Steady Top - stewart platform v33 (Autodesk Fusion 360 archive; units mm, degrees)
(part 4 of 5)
base_feature "Base Feature1"
base_feature "Base Feature1"
base_feature "Base Feature1"
base_feature "Base Feature1"
base_feature "Base Feature1"
base_feature "Base Feature1"
base_feature "Base Feature1"
base_feature "Base Feature1"
base_feature "Base Feature1"
base_feature "Base Feature1"
base_feature "Base Feature1"
base_feature "Base Feature1"
base_feature "Base Feature1"
base_feature "Base Feature1"
base_feature "Base Feature1"
base_feature "Base Feature1"
base_feature "Base Feature1"
base_feature "Base Feature1"
base_feature "Base Feature1"
base_feature "Base Feature1"
base_feature "Base Feature1"
base_feature "Base Feature1"
base_feature "Base Feature1"
base_feature "Base Feature1"
base_feature "Base Feature1"
base_feature "Base Feature1"
base_feature "Base Feature1"
base_feature "Base Feature1"
base_feature "Base Feature1"
base_feature "Base Feature1"
base_feature "Base Feature1"
base_feature "Base Feature1"
base_feature "Base Feature1"
base_feature "Base Feature1"
base_feature "Base Feature1"
base_feature "Base Feature1"
base_feature "Base Feature1"
base_feature "Base Feature1"
base_feature "Base Feature1"
base_feature "Base Feature1"
base_feature "Base Feature1"
base_feature "Base Feature1"
box_primitive "BoxPrimitive1" DistanceX 21.955 DistanceY 11.279 DistanceZ 0.1 OffsetDistanceX 0 OffsetDistanceY 0
base_feature "Base Feature1"
base_feature "Base Feature1"
base_feature "Base Feature1"
base_feature "Base Feature1"
base_feature "Base Feature1"
base_feature "Base Feature1"
base_feature "Base Feature1"
base_feature "Base Feature1"
base_feature "Base Feature1"
base_feature "Base Feature1"
base_feature "Base Feature1"
base_feature "Base Feature1"
base_feature "Base Feature1"
base_feature "Base Feature1"
base_feature "Base Feature1"
base_feature "Base Feature1"
base_feature "Base Feature1"
base_feature "Base Feature1"
base_feature "Base Feature1"
base_feature "Base Feature1"
base_feature "Base Feature1"
base_feature "Base Feature1"
base_feature "Base Feature1"
base_feature "Base Feature1"
base_feature "Base Feature1"
base_feature "Base Feature1"
base_feature "Base Feature1"
base_feature "Base Feature1"
base_feature "Base Feature1"
base_feature "Base Feature1"
base_feature "Base Feature1"
base_feature "Base Feature1"
base_feature "Base Feature1"
base_feature "Base Feature1"
base_feature "Base Feature1"
base_feature "Base Feature1"
base_feature "Base Feature1"
base_feature "Base Feature1"
base_feature "Base Feature1"
base_feature "Base Feature1"
base_feature "Base Feature1"
base_feature "Base Feature1"
base_feature "Base Feature1"
base_feature "Base Feature1"
base_feature "Base Feature1"
base_feature "Base Feature1"
base_feature "Base Feature1"
base_feature "Base Feature1"
base_feature "Base Feature1"
base_feature "Base Feature1"
base_feature "Base Feature1"
base_feature "Base Feature1"
base_feature "Base Feature1"
base_feature "Base Feature1"
base_feature "Base Feature1"
base_feature "Base Feature1"
base_feature "Base Feature1"
base_feature "Base Feature1"
base_feature "Base Feature1"
base_feature "Base Feature1"
base_feature "Base Feature1"
box_primitive "BoxPrimitive1" DistanceX 16.34 DistanceY 13 DistanceZ 0.1 OffsetDistanceX 0 OffsetDistanceY 0
box_primitive "BoxPrimitive1" DistanceX 8 DistanceY 6.35 DistanceZ 0.1 OffsetDistanceX 0 OffsetDistanceY 0
box_primitive "BoxPrimitive1" DistanceX 8.89 DistanceY 6.248 DistanceZ 0.1 OffsetDistanceX 0 OffsetDistanceY 0
box_primitive "BoxPrimitive1" DistanceX 4.572 DistanceY 2.159 DistanceZ 0.1 OffsetDistanceX 0 OffsetDistanceY 0
box_primitive "BoxPrimitive1" DistanceX 4.997 DistanceY 2.017 DistanceZ 0.1 OffsetDistanceX 0 OffsetDistanceY 0
box_primitive "BoxPrimitive1" DistanceX 4.572 DistanceY 2.159 DistanceZ 0.1 OffsetDistanceX 0 OffsetDistanceY 0
box_primitive "BoxPrimitive1" DistanceX 2.54 DistanceY 6.35 DistanceZ 0.1 OffsetDistanceX 0 OffsetDistanceY 0
pcbextrude "PCBExtrude1"
pcbextrude "PCBExtrude1"
pcbextrude "PCBExtrude1"
pcbextrude "PCBExtrude1"
extrude "Extrude1" sketch "Outline(Sketch2)" blind 1.067 bodies "Board"
pcbextrude "PCBExtrude1"
pcbextrude "PCBExtrude2" bodies "CopperHoles"
create_component "CreateComponent1"
create_component "CreateComponent2"
create_component "CreateComponent3"
create_component "CreateComponent4"
create_component "CreateComponent5"
create_component "CreateComponent6"
as_built_joint "As-built1"
create_component "CreateComponent1"
create_component "CreateComponent2"
create_component "CreateComponent3"
create_component "CreateComponent5"
create_component "CreateComponent6"
create_component "CreateComponent7"
create_component "CreateComponent8"
create_component "CreateComponent10"
create_component "CreateComponent1"
create_component "CreateComponent1"
create_component "CreateComponent1"
create_component "CreateComponent2"
create_component "CreateComponent3"
create_component "CreateComponent4"
create_component "CreateComponent1"
create_component "CreateComponent2"
create_component "CreateComponent3"
create_component "CreateComponent4"
create_component "CreateComponent1"
create_component "CreateComponent2"
create_component "CreateComponent3"
create_component "CreateComponent4"
create_component "CreateComponent5"
create_component "CreateComponent6"
create_component "CreateComponent7"
create_component "CreateComponent8"
create_component "CreateComponent9"
create_component "CreateComponent10"
create_component "CreateComponent11"
create_component "CreateComponent12"
create_component "CreateComponent13"
create_component "CreateComponent2"
create_component "CreateComponent1"
create_component "CreateComponent1"
create_component "CreateComponent2"
create_component "CreateComponent2"
create_component "CreateComponent1"
create_component "CreateComponent2"
create_component "CreateComponent3"
create_component "CreateComponent1"
create_component "CreateComponent2"
create_component "CreateComponent3"
create_component "CreateComponent1"
create_component "CreateComponent1"
create_component "CreateComponent2"
create_component "CreateComponent2"
create_component "CreateComponent1"
create_component "CreateComponent2"
create_component "CreateComponent3"
create_component "CreateComponent1"
create_component "CreateComponent2"
create_component "CreateComponent4"
create_component "CreateComponent1"
create_component "CreateComponent2"
create_component "CreateComponent4"
create_component "CreateComponent1"
create_component "CreateComponent1"
create_component "CreateComponent2"
create_component "CreateComponent2"
create_component "CreateComponent1"
create_component "CreateComponent2"
create_component "CreateComponent3"
create_component "CreateComponent1"
create_component "CreateComponent2"
create_component "CreateComponent5"
create_component "CreateComponent1"
create_component "CreateComponent1"
create_component "CreateComponent2"
create_component "CreateComponent2"
create_component "CreateComponent1"
create_component "CreateComponent2"
create_component "CreateComponent3"
create_component "CreateComponent1"
create_component "CreateComponent2"
create_component "CreateComponent4"
create_component "CreateComponent1"
create_component "CreateComponent2"
create_component "CreateComponent6"
create_component "CreateComponent1"
create_component "CreateComponent1"
create_component "CreateComponent1"
create_component "CreateComponent2"
create_component "CreateComponent1"
create_component "CreateComponent3"
create_component "CreateComponent1"
create_component "CreateComponent2"
create_component "CreateComponent1"
create_component "CreateComponent1"
create_component "CreateComponent2"
create_component "CreateComponent1"
create_component "CreateComponent3"
create_component "CreateComponent1"
create_component "CreateComponent4"
create_component "CreateComponent1"
create_component "CreateComponent7"
create_component "CreateComponent1"
create_component "CreateComponent1"
create_component "CreateComponent1"
create_component "CreateComponent2"
create_component "CreateComponent1"
create_component "CreateComponent3"
create_component "CreateComponent1"
create_component "CreateComponent2"
create_component "CreateComponent1"
create_component "CreateComponent1"
create_component "CreateComponent2"
create_component "CreateComponent1"
create_component "CreateComponent3"
create_component "CreateComponent1"
create_component "CreateComponent4"
create_component "CreateComponent1"
create_component "CreateComponent13"
named bodies: "Board", "CopperHoles"

design "815 Servo Driver 16 Channel"
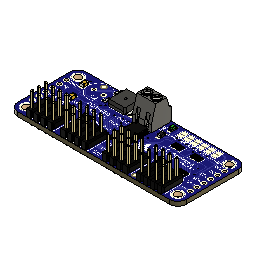
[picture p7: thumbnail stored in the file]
part number: PCA9685
part number: 10K
part number: MOUNTINGHOLE2.5
part number: FIDUCIAL""
part number: AOD417
part number: GREEN
part number: 470
pcb "PCB1" BoardHeight 1.57
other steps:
extrude "Extrude1" new body sketch "Sketch1" along normal blind 0.1 bodies "SOLDERJUMPER_REFLOW_NOPASTE"
extrude "Extrude1" new body sketch "Sketch1" along normal blind 0.1 bodies "MOUNTINGHOLE_2.5_PLATED"
extrude "Extrude1" new body sketch "Sketch1" along normal blind 0.1 bodies "FIDUCIAL_1MM"
extrude "Extrude1" new body sketch "Sketch1" along normal blind 0.1 bodies "E3,5-8"
extrude "Extrude1" new body sketch "Sketch1" along normal blind 0.1 bodies "ADAFRUIT_5MM"
extrude "Extrude1" new body sketch "Sketch1" along normal blind 0.1 bodies "1X06-CLEANBIG"
extrude "Extrude1" new body sketch "Sketch1" along normal blind 0.1 bodies "PCBFEAT-REV-040"
extrude "Extrude1" new body sketch "Sketch1" along normal blind 0.1 bodies "TESTPOINT_ROUND_1MM"
extrude "Extrude1" new body sketch "Sketch1" along normal blind 0.1 bodies "TSSOP28"
extrude "Extrude1" new body sketch "Sketch1" along normal blind 0.1 bodies "TO252"
extrude "Extrude1" new body sketch "Sketch1" along normal blind 0.1 bodies "3X04"
extrude "Extrude1" new body sketch "Sketch1" along normal blind 0.1 bodies "0805-NO"
extrude "Extrude1" new body sketch "Sketch1" along normal blind 0.1 bodies "CHIPLED_0805_NOOUTLINE"
extrude "Extrude1" new body sketch "Sketch1" along normal blind 0.1 bodies "_0805MP"
extrude "Extrude1" new body sketch "Sketch1" along normal blind 0.1 bodies "RESPACK_4X0603"
base_feature "Base Feature1" sketch "Sketch1"
base_feature "Base Feature1" sketch "Sketch1"
base_feature "Base Feature1" sketch "Sketch1"
extrude "Extrude1" new body sketch "Sketch1" along normal blind 1.57 bodies "Board"
base_feature "Base Feature1" sketch "Sketch1"
base_feature "Base Feature1" sketch "Sketch1"
base_feature "Base Feature1" sketch "Sketch1"
base_feature "Base Feature1" sketch "Sketch1"
extrude "Extrude2" sketch "Sketch2" blind 1.57
extrude "Extrude1" new body sketch "Sketch1" along normal blind 0.1 bodies "TERMBLOCK_1X2-3.5MM"
base_feature "Base Feature1" sketch "Sketch1"
create_component "CreateComponent1"
sketch "Sketch1" plane through (0, 0, 0) normal (0, 0, 1) x axis (1, 0, 0)
  line L1 (-1.905, 15.748) -> (-1.905, -3.302)
  line L2 (57.15, 18.923) -> (1.27, 18.923)
  line L3 (60.325, -3.302) -> (60.325, 15.748)
  line L4 (1.27, -6.477) -> (57.15, -6.477)
  arc A1 centre (1.27, -3.302) radius 3.175 clockwise from (1.27, -6.477) to (-1.905, -3.302)
  arc A2 centre (1.27, 15.748) radius 3.175 clockwise from (-1.905, 15.748) to (1.27, 18.923)
  arc A3 centre (57.15, 15.748) radius 3.175 clockwise from (57.15, 18.923) to (60.325, 15.748)
  arc A4 centre (57.15, -3.302) radius 3.175 clockwise from (60.325, -3.302) to (57.15, -6.477)
canvas "Canvas1"
canvas "Canvas2"
sketch "Sketch2" plane through (0, 0, 0) normal (0, 0, 1) x axis (1, 0, 0)
  circle C1 centre (15.24, -2.54) radius 0.25
  circle C2 centre (15.24, -1.27) radius 0.25
  circle C3 centre (15.24, -3.81) radius 0.25
  circle C4 centre (4.953, 16.637) radius 0.197
  circle C5 centre (27.94, 2.667) radius 0.197
  circle C6 centre (33.655, 9.144) radius 0.197
  circle C7 centre (46.482, 13.081) radius 0.197
  circle C8 centre (5.334, 6.731) radius 0.197
  circle C9 centre (50.419, 14.224) radius 0.197
  circle C10 centre (29.083, 10.16) radius 0.197
  circle C11 centre (47.879, 14.224) radius 0.197
  circle C12 centre (24.765, 10.922) radius 0.197
  circle C13 centre (45.339, 14.224) radius 0.197
  circle C14 centre (22.86, 10.795) radius 0.197
  circle C15 centre (42.799, 14.224) radius 0.197
  circle C16 centre (23.876, 9.017) radius 0.197
  circle C17 centre (40.259, 14.224) radius 0.197
  circle C18 centre (20.193, 10.287) radius 0.197
  circle C19 centre (38.989, 14.605) radius 0.197
  circle C20 centre (15.367, 11.811) radius 0.197
  circle C21 centre (30.48, 7.493) radius 0.197
  circle C22 centre (29.464, 6.223) radius 0.197
  circle C23 centre (14.478, 10.795) radius 0.197
  circle C24 centre (52.578, 8.636) radius 0.197
  circle C25 centre (28.575, 5.08) radius 0.197
  circle C26 centre (28.321, 9.017) radius 0.197
  circle C27 centre (53.848, 6.096) radius 0.197
  circle C28 centre (27.41, 15.113) radius 0.5
  circle C29 centre (30.91, 15.113) radius 0.5
  circle C30 centre (1.27, 15.748) radius 1.25
  circle C31 centre (1.27, -3.302) radius 1.25
  circle C32 centre (57.15, 15.748) radius 1.25
  circle C33 centre (57.15, -3.302) radius 1.25
  circle C34 centre (8.128, 14.732) radius 0.4065
  circle C35 centre (11.684, 14.732) radius 0.4065
  circle C36 centre (0, 0) radius 0.508
  circle C37 centre (0, 2.54) radius 0.508
  circle C38 centre (0, 5.08) radius 0.508
  circle C39 centre (0, 7.62) radius 0.508
  circle C40 centre (0, 10.16) radius 0.508
  circle C41 centre (0, 12.7) radius 0.508
  circle C42 centre (58.42, 0) radius 0.508
  circle C43 centre (58.42, 2.54) radius 0.508
  circle C44 centre (58.42, 5.08) radius 0.508
  circle C45 centre (58.42, 7.62) radius 0.508
  circle C46 centre (58.42, 10.16) radius 0.508
  circle C47 centre (58.42, 12.7) radius 0.508
  circle C48 centre (25.4, 0) radius 0.5
  circle C49 centre (25.4, -2.54) radius 0.5
  circle C50 centre (22.86, 0) radius 0.5
  circle C51 centre (22.86, -2.54) radius 0.5
  circle C52 centre (20.32, 0) radius 0.5
  circle C53 centre (20.32, -2.54) radius 0.5
  circle C54 centre (17.78, 0) radius 0.5
  circle C55 centre (17.78, -2.54) radius 0.5
  circle C56 centre (25.4, -5.08) radius 0.5
  circle C57 centre (22.86, -5.08) radius 0.5
  circle C58 centre (20.32, -5.08) radius 0.5
  circle C59 centre (17.78, -5.08) radius 0.5
  circle C60 centre (12.7, 0) radius 0.5
  circle C61 centre (12.7, -2.54) radius 0.5
  circle C62 centre (10.16, 0) radius 0.5
  circle C63 centre (10.16, -2.54) radius 0.5
  circle C64 centre (7.62, 0) radius 0.5
  circle C65 centre (7.62, -2.54) radius 0.5
  circle C66 centre (5.08, 0) radius 0.5
  circle C67 centre (5.08, -2.54) radius 0.5
  circle C68 centre (12.7, -5.08) radius 0.5
  circle C69 centre (10.16, -5.08) radius 0.5
  circle C70 centre (7.62, -5.08) radius 0.5
  circle C71 centre (5.08, -5.08) radius 0.5
  circle C72 centre (53.34, 0) radius 0.5
  circle C73 centre (53.34, -2.54) radius 0.5
  circle C74 centre (50.8, 0) radius 0.5
  circle C75 centre (50.8, -2.54) radius 0.5
  circle C76 centre (48.26, 0) radius 0.5
  circle C77 centre (48.26, -2.54) radius 0.5
  circle C78 centre (45.72, 0) radius 0.5
  circle C79 centre (45.72, -2.54) radius 0.5
  circle C80 centre (53.34, -5.08) radius 0.5
  circle C81 centre (50.8, -5.08) radius 0.5
  circle C82 centre (48.26, -5.08) radius 0.5
  circle C83 centre (45.72, -5.08) radius 0.5
  circle C84 centre (40.64, 0) radius 0.5
  circle C85 centre (40.64, -2.54) radius 0.5
  circle C86 centre (38.1, 0) radius 0.5
  circle C87 centre (38.1, -2.54) radius 0.5
  circle C88 centre (35.56, 0) radius 0.5
  circle C89 centre (35.56, -2.54) radius 0.5
  circle C90 centre (33.02, 0) radius 0.5
  circle C91 centre (33.02, -2.54) radius 0.5
  circle C92 centre (40.64, -5.08) radius 0.5
  circle C93 centre (38.1, -5.08) radius 0.5
  circle C94 centre (35.56, -5.08) radius 0.5
  circle C95 centre (33.02, -5.08) radius 0.5
create_component "CreateComponent2" sketch "Sketch1"
sketch "Sketch1" plane through (0, 0, 0) normal (0, 0, 1) x axis (1, 0, 0)
  line L1 (4.465, -3.121) -> (-4.465, -3.121)
  line L2 (4.465, 3.121) -> (4.465, -3.121)
  line L3 (-4.465, 3.121) -> (4.465, 3.121)
  line L4 (-4.465, -3.121) -> (-4.465, 3.121)
create_component "CreateComponent3" sketch "Sketch1"
sketch "Sketch1" plane through (0, 0, 0) normal (0, 0, 1) x axis (1, 0, 0)
  line L1 (1.651, -1.016) -> (-1.651, -1.016)
  line L2 (1.651, 1.016) -> (1.651, -1.016)
  line L3 (-1.651, 1.016) -> (1.651, 1.016)
  line L4 (-1.651, -1.016) -> (-1.651, 1.016)
create_component "CreateComponent4" sketch "Sketch1"
sketch "Sketch1" plane through (0, 0, 0) normal (0, 0, 1) x axis (1, 0, 0)
  line L1 (1.106, -0.724) -> (-1.092, -0.724)
  line L2 (1.106, 0.726) -> (1.106, -0.724)
  line L3 (-1.092, 0.726) -> (1.106, 0.726)
  line L4 (-1.092, -0.724) -> (-1.092, 0.726)
create_component "CreateComponent5" sketch "Sketch1"
sketch "Sketch1" plane through (0, 0, 0) normal (0, 0, 1) x axis (1, 0, 0)
  line L1 (3.6, -3.6) -> (-3.4, -3.6)
  line L2 (3.6, 3.4) -> (3.6, -3.6)
  line L3 (-3.4, 3.4) -> (3.6, 3.4)
  line L4 (-3.4, -3.6) -> (-3.4, 3.4)
create_component "CreateComponent6" sketch "Sketch1"
sketch "Sketch1" plane through (0, 0, 0) normal (0, 0, 1) x axis (1, 0, 0)
  line L1 (2, -2) -> (-2, -2)
  line L2 (2, 2) -> (2, -2)
  line L3 (-2, 2) -> (2, 2)
  line L4 (-2, -2) -> (-2, 2)
create_component "CreateComponent7" sketch "Sketch1"
sketch "Sketch1" plane through (0, 0, 0) normal (0, 0, 1) x axis (1, 0, 0)
  line L1 (0.75, -0.75) -> (-0.75, -0.75)
  line L2 (0.75, 0.75) -> (0.75, -0.75)
  line L3 (-0.75, 0.75) -> (0.75, 0.75)
  line L4 (-0.75, -0.75) -> (-0.75, 0.75)
create_component "CreateComponent8" sketch "Sketch1"
sketch "Sketch1" plane through (0, 0, 0) normal (0, 0, 1) x axis (1, 0, 0)
  line L1 (3.277, -5.156) -> (-3.277, -5.156)
  line L2 (3.277, 5.105) -> (3.277, -5.156)
  line L3 (-3.277, 5.105) -> (3.277, 5.105)
  line L4 (-3.277, -5.156) -> (-3.277, 5.105)
create_component "CreateComponent9" sketch "Sketch1"
sketch "Sketch1" plane through (0, 0, 0) normal (0, 0, 1) x axis (1, 0, 0)
  line L1 (0.625, -1.3334) -> (-0.625, -1.3334)
  line L2 (0.625, 1.3334) -> (0.625, -1.3334)
  line L3 (-0.625, 1.3334) -> (0.625, 1.3334)
  line L4 (-0.625, -1.3334) -> (-0.625, 1.3334)
create_component "CreateComponent10" sketch "Sketch1"
sketch "Sketch1" plane through (0, 0, 0) normal (0, 0, 1) x axis (1, 0, 0)
  line L1 (1, -0.65) -> (-1, -0.65)
  line L2 (1, 0.65) -> (1, -0.65)
  line L3 (-1, 0.65) -> (1, 0.65)
  line L4 (-1, -0.65) -> (-1, 0.65)
create_component "CreateComponent11" sketch "Sketch1"
sketch "Sketch1" plane through (0, 0, 0) normal (0, 0, 1) x axis (1, 0, 0)
  line L1 (4.064, -4.064) -> (-4.064, -4.064)
  line L2 (4.064, 4.064) -> (4.064, -4.064)
  line L3 (-4.064, 4.064) -> (4.064, 4.064)
  line L4 (-4.064, -4.064) -> (-4.064, 4.064)
create_component "CreateComponent12" sketch "Sketch1"
sketch "Sketch1" plane through (0, 0, 0) normal (0, 0, 1) x axis (1, 0, 0)
  line L1 (4.873, -0.004) -> (-0.004, -0.004)
  line L2 (4.873, 4.865) -> (4.873, -0.004)
  line L3 (-0.004, 4.865) -> (4.873, 4.865)
  line L4 (-0.004, -0.004) -> (-0.004, 4.865)
create_component "CreateComponent13" sketch "Sketch1"
sketch "Sketch1" plane through (0, 0, 0) normal (0, 0, 1) x axis (1, 0, 0)
  line L1 (6.858, -0.508) -> (-6.858, -0.508)
  line L2 (6.858, 0.508) -> (6.858, -0.508)
  line L3 (-6.858, 0.508) -> (6.858, 0.508)
  line L4 (-6.858, -0.508) -> (-6.858, 0.508)
create_component "CreateComponent14" sketch "Sketch1"
sketch "Sketch1" plane through (0, 0, 0) normal (0, 0, 1) x axis (1, 0, 0)
  line L1 (5.08, -3.81) -> (-5.08, -3.81)
  line L2 (5.08, 3.81) -> (5.08, -3.81)
  line L3 (-5.08, 3.81) -> (5.08, 3.81)
  line L4 (-5.08, -3.81) -> (-5.08, 3.81)
create_component "CreateComponent15" sketch "Sketch1"
sketch "Sketch1" plane through (0, 0, 0) normal (0, 0, 1) x axis (1, 0, 0)
  line L1 (1.9, -1.4) -> (-1.9, -1.4)
  line L2 (1.9, 1.4) -> (1.9, -1.4)
  line L3 (-1.9, 1.4) -> (1.9, 1.4)
  line L4 (-1.9, -1.4) -> (-1.9, 1.4)
create_component "CreateComponent16" sketch "Sketch1"
sketch "Sketch1" plane through (0, 0, 0) normal (0, 0, 1) x axis (1, 0, 0)
  line L1 (0.898, -0.898) -> (-0.898, -0.898)
  line L2 (0.898, 0.898) -> (0.898, -0.898)
  line L3 (-0.898, 0.898) -> (0.898, 0.898)
  line L4 (-0.898, -0.898) -> (-0.898, 0.898)
create_component "CreateComponent17" sketch "Sketch1"
sketch "Sketch1" plane through (0, 0, 0) normal (0, 0, 1) x axis (1, 0, 0)
  line L1 (0.7, -0.7) -> (-0.7, -0.7)
  line L2 (0.7, 0.7) -> (0.7, -0.7)
  line L3 (-0.7, 0.7) -> (0.7, 0.7)
  line L4 (-0.7, -0.7) -> (-0.7, 0.7)
as_built_joint "As-built1"
named bodies: "Board", "TSSOP28", "SOLDERJUMPER_REFLOW_NOPASTE", "0805-NO", "TERMBLOCK_1X2-3.5MM", "MOUNTINGHOLE_2.5_PLATED", "FIDUCIAL_1MM", "TO252", "CHIPLED_0805_NOOUTLINE", "_0805MP", "E3,5-8", "ADAFRUIT_5MM", "1X06-CLEANBIG", "3X04", "RESPACK_4X0603", "PCBFEAT-REV-040", "TESTPOINT_ROUND_1MM"

design "SERVO ARM HORN WITH FASTENERS"
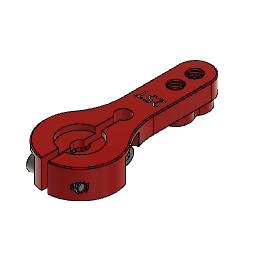
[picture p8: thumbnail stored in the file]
base_feature "Base Feature1"
base_feature "Base Feature1"
position "Position1"
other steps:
create_component "CreateComponent1"
create_component "CreateComponent2"

design "sunfounder_20kgSLDPRT"
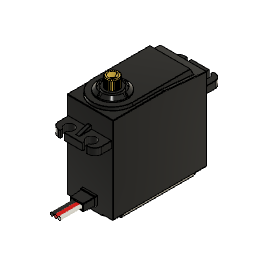
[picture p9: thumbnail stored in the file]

design "KCRM_10_3"
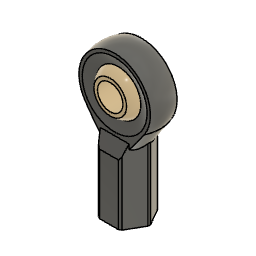
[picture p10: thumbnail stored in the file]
description: STEP AP214
description: PART-2025_05_17_16_37_46_0816-DESC
part number: 2025_05_17_16_37_46_0816
description: PART-2025_05_17_16_37_46_0832-DESC
part number: 2025_05_17_16_37_46_0832
base_feature "Base Feature1"
base_feature "Base Feature1"
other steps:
create_component "CreateComponent1"
create_component "CreateComponent2"

design "Fab Board"
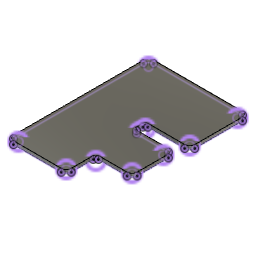
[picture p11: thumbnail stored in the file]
sketch "Sketch1" plane through (0, 0, 0) normal (0, 0, 1) x axis (1, 0, 0)
  line L1 (-17.5, 42.5) -> (17.5, 42.5)
  line L2 (-17.5, -42.5) -> (-17.5, 42.5)
  line L3 (17.5, -42.5) -> (-17.5, -42.5)
  line L4 (17.5, 42.5) -> (17.5, -42.5)
  line L5 (-17.5, -42.5) -> (17.5, 42.5)
  line L6 (17.5, -42.5) -> (-17.5, 42.5)
  line L7 (42.5, 42.5) -> (17.5, 42.5)
  line L8 (42.5, 7.5) -> (42.5, 42.5)
  line L9 (17.5, 7.5) -> (42.5, 7.5)
  line L10 (17.5, 42.5) -> (17.5, 7.5)
  line L11 (39.5, 0.5) -> (17.5, 0.5)
  line L12 (39.5, -24.5) -> (39.5, 0.5)
  line L13 (17.5, -24.5) -> (39.5, -24.5)
  line L14 (17.5, 0.5) -> (17.5, -24.5)
  point P6 (0, 0)
  point P1 (0, 0)
  point P13 (17.5, -24.5)
  point P4 (-17.5, -42.5)
  point P5 (17.5, -42.5)
  point P3 (-17.5, 42.5)
  point P2 (17.5, 42.5)
  point P7 (42.5, 42.5)
  point P11 (39.5, 0.5)
  point P12 (39.5, -24.5)
  horizontal L1
  perpendicular L1 L2
  parallel L1 L3
  parallel L2 L4
  coincident L5 P6
  coincident L6 P6
  coincident P1 P6
  horizontal L7
  vertical L8
  horizontal L9
  vertical L10
  horizontal L11
  vertical L12
  horizontal L13
  vertical L14
  equal L1 L8
  coincident L4 P13
  dimension "d1" distance P4 P5 = 35
  dimension "d2" distance P3 P4 = 85
  dimension "d3" distance P2 P7 = 25
  dimension "d8" distance P11 P12 = 25
  dimension "d9" distance L9 L11 = 7
  dimension "d10" distance L8 L12 = 3
extrude "Extrude1" new body sketch "Sketch1" profile of L1 L2 L3 L4 L7 L8 L9 L10 L11 L12 L13 L14 along normal blind 2
fillet "Fillet1" radius 3
fillet "Fillet2" radius 1.6
offset_faces "OffsetFaces1" distance -2
sketch "Sketch2" plane through (0, 0, 0) normal (0, 0, 1) x axis (1, 0, 0)
  line L1 (-14.5, 42.5) -> (39.5, 42.5)
  line L2 (-17.5, -39.5) -> (-17.5, 39.5)
  line L3 (14.5, -42.5) -> (-14.5, -42.5)
  line L4 (17.5, -26.1) -> (17.5, -39.5)
  line L5 (36.5, -24.5) -> (19.1, -24.5)
  line L6 (39.5, -2.5) -> (39.5, -21.5)
  line L7 (17.1, 0.5) -> (36.5, 0.5)
  line L8 (15.5, 5.9) -> (15.5, 2.1)
  line L9 (39.5, 7.5) -> (17.1, 7.5)
  line L10 (42.5, 39.5) -> (42.5, 10.5)
  arc A1 centre (39.5, 39.5) radius 3 clockwise from (39.5, 42.5) to (42.5, 39.5)
  arc A2 centre (-14.5, 39.5) radius 3 clockwise from (-17.5, 39.5) to (-14.5, 42.5)
  arc A3 centre (-14.5, -39.5) radius 3 clockwise from (-14.5, -42.5) to (-17.5, -39.5)
  arc A4 centre (14.5, -39.5) radius 3 clockwise from (17.5, -39.5) to (14.5, -42.5)
  arc A5 centre (36.5, -21.5) radius 3 clockwise from (39.5, -21.5) to (36.5, -24.5)
  arc A6 centre (36.5, -2.5) radius 3 clockwise from (36.5, 0.5) to (39.5, -2.5)
  arc A7 centre (39.5, 10.5) radius 3 clockwise from (42.5, 10.5) to (39.5, 7.5)
  arc A8 centre (19.1, -26.1) radius 1.6 clockwise from (17.5, -26.1) to (19.1, -24.5)
  arc A9 centre (17.1, 2.1) radius 1.6 clockwise from (17.1, 0.5) to (15.5, 2.1)
  arc A10 centre (17.1, 5.9) radius 1.6 clockwise from (15.5, 5.9) to (17.1, 7.5)

design "Meanwell RSP-150-7.5"
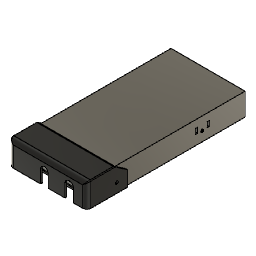
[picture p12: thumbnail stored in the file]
sketch "Sketch1" plane through (0, 0, 0) normal (0, 0, 1) x axis (1, 0, 0)
canvas "Canvas1"
sketch "Sketch2" plane through (0, 0, 0) normal (0, 0, 1) x axis (1, 0, 0)
  line L1 (49.5, -69.9887) -> (-49.5, -69.9887)
  line L2 (49.5, 129.0113) -> (49.5, -69.9887)
  line L3 (-49.5, 129.0113) -> (49.5, 129.0113)
  line L4 (-49.5, -69.9887) -> (-49.5, 129.0113)
  line L5 (-49.5, -55.2389) -> (49.5, -55.2389)
  line L6 (47.5, 129.0113) -> (47.5, -69.9887)
  line L7 (-47.5, -69.9887) -> (-47.5, 129.0113)
  line L8 (0, 129.0113) -> (0, 0)
  point P6 (49.5, -55.2389)
  point P7 (-49.5, -55.2389)
  point P8 (47.5, -69.9887)
  point P9 (47.5, 129.0113)
  point P10 (-47.5, 129.0113)
  point P11 (-47.5, -69.9887)
  point P1 (0, 0)
  point P12 (0, 0)
  point P13 (0, 129.0113)
  point P4 (49.5, 129.0113)
  point P5 (-49.5, 129.0113)
  point P2 (-49.5, -69.9887)
  horizontal L1
  vertical L2
  horizontal L3
  vertical L4
  coincident L2 P6
  coincident L4 P7
  perpendicular L4 L5
  coincident L1 P8
  coincident L3 P9
  perpendicular L3 L6
  coincident L3 P10
  coincident L1 P11
  perpendicular L1 L7
  coincident P1 P12
  midpoint L3 P13
  vertical L8
  dimension "d1" distance P4 P5 = 99
  dimension "d2" distance P2 P5 = 199
  dimension "d50" distance L4 L7 = 2
  dimension "d51" distance L2 L6 = 2
extrude "Extrude1" new body sketch "Sketch2" profile of L1 L2 L3 L4 L5 L6 L7 along normal blind 30
extrude "Extrude2" add sketch "Sketch2" profile of L1 L5 L6 L7 along normal blind 2
sketch "Sketch3" plane through (49.5, 0, 0) normal (1, 0, 0) x axis (0, 1, 0)
  line L1 (129.0113, 0) -> (-69.9887, 0)
  line L2 (129.0113, 30) -> (129.0113, 0)
  line L3 (-69.9887, 30) -> (129.0113, 30)
  line L4 (-69.9887, 0) -> (-69.9887, 30)
  line L5 (-44.9887, 30) -> (-44.9887, 0)
  line L6 (72.0113, 30) -> (72.0113, 0)
  line L7 (72.0113, 12.5) -> (-44.9887, 12.5)
  line L8 (129.0113, 0) -> (-69.9887, 0)
  line L9 (-35.9887, 13.1) -> (-38.4887, 13.1)
  line L10 (-35.9887, 20) -> (-35.9887, 13.1)
  line L11 (-38.4887, 20) -> (-35.9887, 20)
  line L12 (-38.4887, 13.1) -> (-38.4887, 20)
  line L13 (-51.4887, 13.1) -> (-51.4887, 20)
  line L14 (-53.9887, 13.1) -> (-51.4887, 13.1)
  line L15 (-51.4887, 20) -> (-53.9887, 20)
  line L16 (-53.9887, 20) -> (-53.9887, 13.1)
  line L17 (13.5113, 43.3895) -> (13.5113, 12.5)
  line L18 (81.0113, 20) -> (81.0113, 13.1)
  line L19 (78.5113, 20) -> (81.0113, 20)
  line L20 (78.5113, 13.1) -> (78.5113, 20)
  line L21 (81.0113, 13.1) -> (78.5113, 13.1)
  line L22 (65.5113, 13.1) -> (65.5113, 20)
  line L23 (63.0113, 13.1) -> (65.5113, 13.1)
  line L24 (65.5113, 20) -> (63.0113, 20)
  line L25 (63.0113, 20) -> (63.0113, 13.1)
  circle C1 centre (72.0113, 12.5) radius 2
  circle C2 centre (-44.9887, 12.5) radius 2
  point P6 (-44.9887, 0)
  point P7 (-44.9887, 30)
  point P8 (72.0113, 0)
  point P9 (72.0113, 30)
  point P10 (-44.9887, 12.5)
  point P11 (72.0113, 12.5)
  point P14 (72.0113, 12.5)
  point P15 (-44.9887, 12.5)
  point P16 (-38.4887, 13.1)
  point P21 (-51.4887, 13.1)
  point P17 (-35.9887, 13.1)
  point P22 (-53.9887, 13.1)
  point P18 (-35.9887, 20)
  point P23 (-53.9887, 20)
  point P19 (-38.4887, 20)
  point P20 (-51.4887, 20)
  point P24 (13.5113, 12.5)
  point P31 (65.5113, 13.1)
  point P32 (63.0113, 13.1)
  point P33 (63.0113, 20)
  point P30 (65.5113, 20)
  point P28 (78.5113, 20)
  point P29 (78.5113, 13.1)
  point P26 (81.0113, 13.1)
  point P27 (81.0113, 20)
  coincident L1 P6
  coincident L3 P7
  perpendicular L3 L5
  coincident L1 P8
  coincident L3 P9
  perpendicular L3 L6
  coincident L5 P10
  coincident L6 P11
  perpendicular L6 L7
  coincident P11 P14
  coincident P10 P15
  equal C1 C2
  horizontal L9
  vertical L10
  horizontal L11
  vertical L12
  symmetric L5 P16 P21
  symmetric L5 P17 P22
  symmetric L5 P18 P23
  symmetric L5 P19 P20
  midpoint L7 P24
  perpendicular L7 L17
  symmetric P16 L17 P31
  symmetric P17 L17 P32
  symmetric P18 L17 P33
  symmetric P19 L17 P30
  symmetric P20 L17 P28
  symmetric P21 L17 P29
  symmetric P22 L17 P26
  symmetric P23 L17 P27
  dimension "d7" distance L4 L5 = 25
  dimension "d8" distance L5 L6 = 117
  dimension "d9" distance L7 L8 = 12.5
  dimension "d10" diameter C1 = 4
  dimension "d15" distance P17 P18 = 6.9
  dimension "d16" distance P18 P19 = 2.5
  dimension "d17" distance L5 L12 = 6.5
  dimension "d19" distance L3 L11 = 10
extrude "Extrude3" cut sketch "Sketch3" profile of C1 C2 L9 L10 L11 L12 L13 L14 L15 L16 L18 L19 L20 L21 L22 L23 L24 L25 against normal blind 4
mirror "Mirror1" mirrorStitchTolerance 0.1
sketch "Sketch5" plane through (0, 0, 2) normal (0, 0, 1) x axis (-1, 0, 0)
  line L1 (47.5, 55.2389) -> (-47.5, 55.2389)
  line L2 (47.5, 69.9887) -> (47.5, 55.2389)
  line L3 (-47.5, 69.9887) -> (47.5, 69.9887)
  line L4 (-47.5, 55.2389) -> (-47.5, 69.9887)
  line L5 (-43.7071, 68.3467) -> (25.3054, 68.3467)
  line L6 (-43.7071, 53.8985) -> (-43.7071, 68.3467)
  line L7 (25.3054, 53.8985) -> (-43.7071, 53.8985)
  line L8 (25.3054, 68.3467) -> (25.3054, 53.8985)
  line L9 (15.433, 68.3467) -> (23.3131, 68.3467)
  line L10 (15.433, 55.2389) -> (15.433, 68.3467)
  line L11 (23.3131, 55.2389) -> (15.433, 55.2389)
  line L12 (23.3131, 68.3467) -> (23.3131, 55.2389)
  line L13 (13.7931, 68.3467) -> (13.7931, 55.2389)
  line L14 (5.913, 68.3467) -> (13.7931, 68.3467)
  line L15 (5.913, 55.2389) -> (5.913, 68.3467)
  line L16 (13.7931, 55.2389) -> (5.913, 55.2389)
  line L17 (4.2731, 68.3467) -> (4.2731, 55.2389)
  line L18 (-3.607, 68.3467) -> (4.2731, 68.3467)
  line L19 (-3.607, 55.2389) -> (-3.607, 68.3467)
  line L20 (4.2731, 55.2389) -> (-3.607, 55.2389)
  line L21 (-5.2469, 68.3467) -> (-5.2469, 55.2389)
  line L22 (-13.127, 68.3467) -> (-5.2469, 68.3467)
  line L23 (-13.127, 55.2389) -> (-13.127, 68.3467)
  line L24 (-5.2469, 55.2389) -> (-13.127, 55.2389)
  line L25 (-14.7669, 68.3467) -> (-14.7669, 55.2389)
  line L26 (-22.647, 68.3467) -> (-14.7669, 68.3467)
  line L27 (-22.647, 55.2389) -> (-22.647, 68.3467)
  line L28 (-14.7669, 55.2389) -> (-22.647, 55.2389)
  line L29 (-24.2869, 68.3467) -> (-24.2869, 55.2389)
  line L30 (-32.167, 68.3467) -> (-24.2869, 68.3467)
  line L31 (-32.167, 55.2389) -> (-32.167, 68.3467)
  line L32 (-24.2869, 55.2389) -> (-32.167, 55.2389)
  line L33 (-33.8069, 68.3467) -> (-33.8069, 55.2389)
  line L34 (-41.687, 68.3467) -> (-33.8069, 68.3467)
  line L35 (-41.687, 55.2389) -> (-41.687, 68.3467)
  line L36 (-33.8069, 55.2389) -> (-41.687, 55.2389)
  point P12 (15.433, 55.2389)
  point P10 (23.3131, 68.3467)
  horizontal L5
  vertical L6
  horizontal L7
  vertical L8
  horizontal L9
  vertical L10
  horizontal L11
  vertical L12
  coincident L1 P12
  coincident L5 P10
  dimension "d22" R-Pattern1-uDistance = -9.52
  dimension "d23" R-Pattern1-vDistance = 0
extrude "Extrude4" add sketch "Sketch5" profile of L1 L5 L6 L8 L10 L12 L13 L15 L17 L19 L21 L23 L25 L27 L29 L31 L32 L33 L35 along normal blind 19.5
extrude "Extrude5" add sketch "Sketch5" profile of L1 L5 L9 L10 L11 L12 L13 L14 L15 L16 L17 L18 L19 L20 L21 L22 L23 L24 L25 L26 L27 L28 L29 L30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 along normal blind 12
sketch "Sketch6" plane through (0, 0, 0) normal (0, 0, 1) x axis (1, 0, 0)
  line L1 (0, 65) -> (0, 0)
  circle C1 centre (0, 65) radius 2
  circle C2 centre (0, 0) radius 2
  point P1 (0, 0)
  point P3 (0, 0)
  point P4 (0, 0)
  point P2 (0, 65)
  point P5 (0, 65)
  coincident P1 P3
  coincident P1 P4
  coincident P2 P5
  vertical L1
  equal C1 C2
  dimension "d28" diameter C2 = 4
  dimension "d29" distance P4 P5 = 65
extrude "Extrude6" cut sketch "Sketch6" profile of C1 C2 along normal blind 4
thread "Thread1" ThreadOffset 0 ThreadLength 10
sketch "Sketch7" plane through (0, 0, 30) normal (0, 0, 1) x axis (-1, 0, 0)
  line L1 (-49.5, 69.9887) -> (-47.5, 69.9887)
  line L2 (-49.5, -129.0113) -> (-49.5, 69.9887)
  line L3 (49.5, -129.0113) -> (-49.5, -129.0113)
  line L4 (49.5, 69.9887) -> (49.5, -129.0113)
  line L5 (47.5, 69.9887) -> (49.5, 69.9887)
  line L6 (47.5, 55.2389) -> (47.5, 69.9887)
  line L7 (-47.5, 55.2389) -> (47.5, 55.2389)
  line L8 (-47.5, 69.9887) -> (-47.5, 55.2389)
  line L9 (-52, 44.9887) -> (52, 44.9887)
  line L10 (-52, 84.9887) -> (-52, 44.9887)
  line L11 (52, 84.9887) -> (-52, 84.9887)
  line L12 (52, 44.9887) -> (52, 84.9887)
  point P11 (-52, 44.9887)
  point P12 (-52, 84.9887)
  point P3 (-49.5, 69.9887)
  horizontal L9
  vertical L10
  horizontal L11
  vertical L12
  dimension "d34" distance L2 L10 = 2.5
  dimension "d35" distance L4 L12 = 2.5
  dimension "d36" distance P11 P12 = 40
  dimension "d37" distance P3 L9 = 25
extrude "Extrude7" new body sketch "Sketch7" profile of L1 L2 L4 L5 L6 L7 L8 L9 L10 L11 L12 along normal blind 2.5
sketch "Sketch8" plane through (49.5, 0, 0) normal (1, 0, 0) x axis (0, 1, 0)
  curve K1 (-46.2578, 13.5794) -> (-45.5189, 10.5148)
  curve K2 (-44.4586, 10.5148) -> (-43.7197, 13.5794)
  curve K3 (70.7422, 13.5794) -> (71.4811, 10.5148)
  curve K4 (72.5414, 10.5148) -> (73.2803, 13.5794)
  line L1 (-38.4887, 13.1) -> (-35.9887, 13.1)
  line L2 (-38.4887, 20) -> (-38.4887, 13.1)
  line L3 (-35.9887, 20) -> (-38.4887, 20)
  line L4 (-35.9887, 13.1) -> (-35.9887, 20)
  line L5 (65.5113, 13.1) -> (65.5113, 20)
  line L6 (63.0113, 13.1) -> (65.5113, 13.1)
  line L7 (63.0113, 20) -> (63.0113, 13.1)
  line L8 (65.5113, 20) -> (63.0113, 20)
  line L9 (-51.4887, 13.1) -> (-51.4887, 20)
  line L10 (-53.9887, 13.1) -> (-51.4887, 13.1)
  line L11 (-53.9887, 20) -> (-53.9887, 13.1)
  line L12 (-51.4887, 20) -> (-53.9887, 20)
  line L13 (81.0113, 13.1) -> (81.0113, 20)
  line L14 (78.5113, 13.1) -> (81.0113, 13.1)
  line L15 (78.5113, 20) -> (78.5113, 13.1)
  line L16 (81.0113, 20) -> (78.5113, 20)
  line L17 (129.0113, 0) -> (-69.9887, 0)
  line L18 (129.0113, 30) -> (129.0113, 0)
  line L19 (-69.9887, 30) -> (129.0113, 30)
  line L20 (-69.9887, 0) -> (-69.9887, 30)
  line L21 (-44.9887, 30) -> (-84.9887, 30)
  line L22 (-44.9887, 32.5) -> (-44.9887, 30)
  line L23 (-84.9887, 32.5) -> (-44.9887, 32.5)
  line L24 (-84.9887, 30) -> (-84.9887, 32.5)
  line L25 (-30.4006, 30) -> (-84.9887, 30)
  line L26 (-30.4006, 0) -> (-30.4006, 30)
  line L27 (-84.9887, 0) -> (-30.4006, 0)
  line L28 (-84.9887, 30) -> (-84.9887, 0)
  line L29 (-30.4006, 20.1056) -> (-48.6747, 32.5)
  arc A1 centre (-44.9887, 12.5) radius 1.666 clockwise from (-46.2578, 13.5794) to (-43.7197, 13.5794)
  arc A2 centre (-44.9887, 12.5) radius 2.0548 clockwise from (-44.4586, 10.5148) to (-45.5189, 10.5148)
  arc A3 centre (72.0113, 12.5) radius 1.666 clockwise from (70.7422, 13.5794) to (73.2803, 13.5794)
  arc A4 centre (72.0113, 12.5) radius 2.0548 clockwise from (72.5414, 10.5148) to (71.4811, 10.5148)
  circle C1 centre (-44.9887, 12.5) radius 2
  point P38 (-30.4006, 0)
  point P32 (-84.9887, 30)
  point P36 (-84.9887, 30)
  point P40 (-30.4006, 20.1056)
  point P41 (-48.6747, 32.5)
  horizontal L25
  vertical L26
  horizontal L27
  vertical L28
  coincident L17 P38
  coincident P32 P36
  coincident L26 P40
  coincident L23 P41
extrude "Extrude8" add sketch "Sketch8" profile of K1 K2 A2 L1 L2 L3 L4 L9 L10 L11 L12 L17 L19 L20 L21 L25 L26 L27 L28 L29 C1 along normal blind 2.5
sketch "Sketch9" plane through (49.5, 0, 0) normal (-1, 0, 0) x axis (0, -1, 0)
  line L1 (53.9887, 13.1) -> (53.9887, 20)
  line L2 (51.4887, 13.1) -> (53.9887, 13.1)
  line L3 (51.4887, 20) -> (51.4887, 13.1)
  line L4 (53.9887, 20) -> (51.4887, 20)
  line L5 (38.4887, 20) -> (35.9887, 20)
  line L6 (38.4887, 13.1) -> (38.4887, 20)
  line L7 (35.9887, 13.1) -> (38.4887, 13.1)
  line L8 (35.9887, 20) -> (35.9887, 13.1)
  curve K1 (44.4586, 10.5148) -> (43.9524, 10.7894)
  curve K2 (46.0251, 10.7894) -> (45.5189, 10.5148)
  line L9 (44.9887, 30) -> (84.9887, 30)
  line L10 (30.4006, 20.1056) -> (44.9887, 30)
  line L11 (30.4006, 0) -> (30.4006, 20.1056)
  line L12 (84.9887, 0) -> (30.4006, 0)
  line L13 (84.9887, 30) -> (84.9887, 0)
  line L14 (51.6637, 13.275) -> (53.8137, 13.275)
  line L15 (51.6637, 19.825) -> (51.6637, 13.275)
  line L16 (53.8137, 19.825) -> (51.6637, 19.825)
  line L17 (53.8137, 13.275) -> (53.8137, 19.825)
  line L18 (36.1637, 19.825) -> (36.1637, 13.275)
  line L19 (38.3137, 19.825) -> (36.1637, 19.825)
  line L20 (38.3137, 13.275) -> (38.3137, 19.825)
  line L21 (36.1637, 13.275) -> (38.3137, 13.275)
  arc A1 centre (44.9887, 12.5) radius 2.0548 clockwise from (45.5189, 10.5148) to (44.4586, 10.5148)
  arc A2 centre (44.9887, 12.5) radius 2 clockwise from (43.9524, 10.7894) to (46.0251, 10.7894)
  dimension "d42" = 0.175
  dimension "d43" = 0.175
extrude "Extrude9" add sketch "Sketch9" profile of L1 L2 L3 L4 L5 L6 L7 L8 L14 L15 L16 L17 L21 L20 L19 L18 against normal blind 2.5
extrude "Extrude10" add sketch "Sketch9" profile of L14 L15 L16 L17 L21 L20 L19 L18 along normal blind 1.5
mirror "Mirror2" mirrorStitchTolerance 0.1
chamfer "Chamfer1" distance 3.8 distance 2.5
sketch "Sketch10" plane through (0, -84.9887, 0) normal (0, -1, 0) x axis (1, 0, 0)
  line L1 (52, 32.5) -> (52, 0)
  line L2 (-52, 32.5) -> (52, 32.5)
  line L3 (-52, 0) -> (-52, 32.5)
  line L4 (-49.5, 0) -> (-52, 0)
  line L5 (-49.5, 30) -> (-49.5, 0)
  line L6 (49.5, 30) -> (-49.5, 30)
  line L7 (49.5, 0) -> (49.5, 30)
  line L8 (52, 0) -> (49.5, 0)
  line L9 (49.5, 0) -> (-49.5, 0)
  line L10 (34.0292, 22.5874) -> (22.6413, 22.5874)
  line L11 (34.0292, 0) -> (34.0292, 22.5874)
  line L12 (22.6413, 0) -> (34.0292, 0)
  line L13 (22.6413, 22.5874) -> (22.6413, 0)
  line L14 (0.1205, 22.5476) -> (-9.956, 22.5476)
  line L15 (0.1205, 0) -> (0.1205, 22.5476)
  line L16 (-9.956, 0) -> (0.1205, 0)
  line L17 (-9.956, 22.5476) -> (-9.956, 0)
  point P6 (-49.5, 0)
  point P10 (-49.5, 0)
  point P9 (49.5, 0)
  point P11 (49.5, 0)
  point P14 (34.0292, 0)
  point P18 (0.1205, 0)
  coincident P6 P10
  coincident P9 P11
  horizontal L10
  vertical L11
  horizontal L12
  vertical L13
  coincident L9 P14
  horizontal L14
  vertical L15
  horizontal L16
  vertical L17
  coincident L9 P18
extrude "Extrude11" add sketch "Sketch10" profile of L5 L6 L7 L9 L10 L11 L13 L14 L15 L17 against normal blind 2.5
fillet "Fillet1" radius 5
fillet "Fillet2" radius 0.5
fillet "Fillet3" radius 3.5
fillet "Fillet4" radius 1
fillet "Fillet5" radius 5.5
chamfer "Chamfer2" distance 1.2
sketch "Sketch4" plane through (49.5571, 0, 0) normal (1, 0, 0) x axis (0, 1, 0)
  line L1 (129.0113, 0) -> (-69.9887, 0)
  line L2 (129.0113, 30) -> (129.0113, 0)
  line L3 (-69.9887, 30) -> (129.0113, 30)
  line L4 (-69.9887, 0) -> (-69.9887, 30)
  circle C1 centre (-44.9887, 12.5) radius 2
  circle C2 centre (72.0113, 12.5) radius 2
named bodies: "Power Supply Cover"

design "L servo horn"
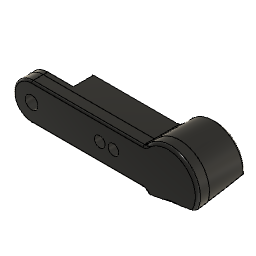
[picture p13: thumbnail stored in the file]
base_feature "Base Feature3"
base_feature "Base Feature1" bodies "L Back"
copy_paste_bodies "CutPasteBodies"
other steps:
base_feature "Base Feature2" bodies "L Front"
named bodies: "L Back", "L Front"

design "GZRM_06_IG_6"
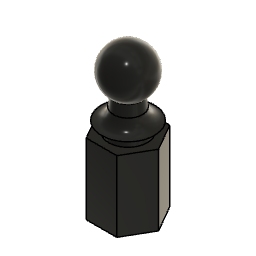
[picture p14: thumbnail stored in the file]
description: STEP AP214
part number: 2025_05_17_16_39_25_0877
base_feature "Base Feature"

design "BNO085 STEMMA QT"
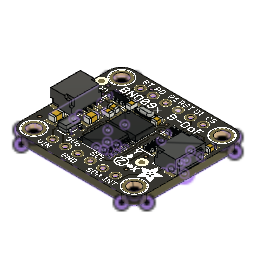
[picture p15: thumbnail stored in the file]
part number: 10uF
part number: AP2112K-3.3
part number: 22pF
part number: 10K
part number: BSS138
part number: MOUNTINGHOLE2.5
part number: STEMMA_I2C_QT
part number: FIDUCIAL_1MM
part number: GREEN
part number: BNO080
part number: 32.768
part number: PS0
part number: 74AHC4050
derived_context "DerivedContext1"
pcb "PCB1" BoardHeight 1.57
sketch "Sketch1" plane through (0, 0, 0) normal (0, 0, -1) x axis (1, 0, 0)
  line L1 (22.86, -22.86) -> (2.54, -22.86)
  line L2 (25.4, -2.54) -> (25.4, -20.32)
  line L3 (2.54, 0) -> (22.86, 0)
  line L4 (0, -20.32) -> (0, -2.54)
  line L5 (2.54, -22.86) -> (22.86, -22.86)
  line L6 (25.4, -20.32) -> (25.4, -2.54)
  line L7 (22.86, 0) -> (2.54, 0)
  line L8 (0, -2.54) -> (0, -20.32)
  line L9 (2.54, -2.54) -> (22.86, -20.32)
  line L10 (2.54, -20.32) -> (2.54, -2.54)
  line L11 (22.86, -2.54) -> (2.54, -20.32)
  line L12 (12.7, -21.0513) -> (12.7, -11.43)
  circle C1 centre (2.54, -2.54) radius 1.25
  circle C2 centre (2.54, -20.32) radius 1.25
  circle C3 centre (16.51, -20.32) radius 0.5
  circle C4 centre (11.43, -20.32) radius 0.5
  circle C5 centre (6.35, -20.32) radius 0.5
  circle C6 centre (16.51, -2.54) radius 0.5
  circle C7 centre (11.43, -2.54) radius 0.5
  circle C8 centre (6.35, -2.54) radius 0.5
  circle C9 centre (13.906, -5.207) radius 0.2415
  circle C10 centre (13.843, -6.414) radius 0.2415
  circle C11 centre (11.806, -7.43) radius 0.2415
  circle C12 centre (1.016, -5.207) radius 0.2415
  circle C13 centre (8.779, -11.267) radius 0.197
  circle C14 centre (21.952, -10.922) radius 0.2415
  circle C15 centre (13.843, -9.652) radius 0.2415
  circle C16 centre (9.55, -13.931) radius 0.2415
  circle C17 centre (10.782, -9.144) radius 0.2415
  circle C18 centre (21.886, -12.785) radius 0.2415
  circle C19 centre (3.251, -11.155) radius 0.2415
  circle C20 centre (7.62, -21.209) radius 0.2415
  circle C21 centre (4.636, -13.97) radius 0.2415
  circle C22 centre (2.604, -17.462) radius 0.2415
  circle C23 centre (19.05, -4.699) radius 0.2415
  circle C24 centre (24.13, -11.366) radius 0.2415
  circle C25 centre (15.367, -16.574) radius 0.2415
  circle C26 centre (15.938, -14.922) radius 0.2415
  circle C27 centre (21.844, -9.462) radius 0.2415
  circle C28 centre (20.764, -16.002) radius 0.2415
  circle C29 centre (3.302, -9.842) radius 0.2415
  circle C30 centre (6.032, -7.556) radius 0.2415
  circle C31 centre (22.924, -16.002) radius 0.2415
  circle C32 centre (21.958, -13.906) radius 0.2415
  circle C33 centre (3.391, -15.43) radius 0.2415
  circle C34 centre (12.256, -9.588) radius 0.197
  circle C35 centre (10.668, -7.048) radius 0.2415
  circle C36 centre (13.843, -7.861) radius 0.2415
  circle C37 centre (11.303, -5.448) radius 0.2415
  circle C38 centre (18.86, -8.89) radius 0.2415
  circle C39 centre (8.89, -2.54) radius 0.5
  circle C40 centre (13.97, -2.54) radius 0.5
  circle C41 centre (19.05, -2.54) radius 0.5
  circle C42 centre (8.89, -20.32) radius 0.5
  circle C43 centre (13.97, -20.32) radius 0.5
  circle C44 centre (19.05, -20.32) radius 0.5
  circle C45 centre (22.86, -20.32) radius 1.25
  circle C46 centre (22.86, -2.54) radius 1.25
  arc A1 centre (2.54, -20.32) radius 2.54 clockwise from (2.54, -22.86) to (0, -20.32)
  arc A2 centre (22.86, -20.32) radius 2.54 clockwise from (25.4, -20.32) to (22.86, -22.86)
  arc A3 centre (22.86, -2.54) radius 2.54 clockwise from (22.86, 0) to (25.4, -2.54)
  arc A4 centre (2.54, -2.54) radius 2.54 clockwise from (0, -2.54) to (2.54, 0)
  circle C47 centre (2.54, -2.54) radius 1.25
  circle C48 centre (2.54, -20.32) radius 1.25
  circle C49 centre (16.51, -20.32) radius 0.5
  circle C50 centre (11.43, -20.32) radius 0.5
  circle C51 centre (6.35, -20.32) radius 0.5
  circle C52 centre (16.51, -2.54) radius 0.5
  circle C53 centre (11.43, -2.54) radius 0.5
  circle C54 centre (6.35, -2.54) radius 0.5
  circle C55 centre (13.906, -5.207) radius 0.2415
  circle C56 centre (13.843, -6.414) radius 0.2415
  circle C57 centre (11.806, -7.43) radius 0.2415
  circle C58 centre (1.016, -5.207) radius 0.2415
  circle C59 centre (8.779, -11.267) radius 0.197
  circle C60 centre (21.952, -10.922) radius 0.2415
  circle C61 centre (13.843, -9.652) radius 0.2415
  circle C62 centre (9.55, -13.931) radius 0.2415
  circle C63 centre (10.782, -9.144) radius 0.2415
  circle C64 centre (21.886, -12.785) radius 0.2415
  circle C65 centre (3.251, -11.155) radius 0.2415
  circle C66 centre (7.62, -21.209) radius 0.2415
  circle C67 centre (4.636, -13.97) radius 0.2415
  circle C68 centre (2.604, -17.462) radius 0.2415
  circle C69 centre (19.05, -4.699) radius 0.2415
  circle C70 centre (24.13, -11.366) radius 0.2415
  circle C71 centre (15.367, -16.574) radius 0.2415
  circle C72 centre (15.938, -14.922) radius 0.2415
  circle C73 centre (21.844, -9.462) radius 0.2415
  circle C74 centre (20.764, -16.002) radius 0.2415
  circle C75 centre (3.302, -9.842) radius 0.2415
  circle C76 centre (6.032, -7.556) radius 0.2415
  circle C77 centre (22.924, -16.002) radius 0.2415
  circle C78 centre (21.958, -13.906) radius 0.2415
  circle C79 centre (3.391, -15.43) radius 0.2415
  circle C80 centre (12.256, -9.588) radius 0.197
  circle C81 centre (10.668, -7.048) radius 0.2415
  circle C82 centre (13.843, -7.861) radius 0.2415
  circle C83 centre (11.303, -5.448) radius 0.2415
  circle C84 centre (18.86, -8.89) radius 0.2415
  circle C85 centre (8.89, -2.54) radius 0.5
  circle C86 centre (13.97, -2.54) radius 0.5
  circle C87 centre (19.05, -2.54) radius 0.5
  circle C88 centre (8.89, -20.32) radius 0.5
  circle C89 centre (13.97, -20.32) radius 0.5
  circle C90 centre (19.05, -20.32) radius 0.5
  circle C91 centre (22.86, -20.32) radius 1.25
  circle C92 centre (22.86, -2.54) radius 1.25
  arc A5 centre (22.86, -20.32) radius 2.54 clockwise from (25.4, -20.32) to (22.86, -22.86)
  arc A6 centre (22.86, -2.54) radius 2.54 clockwise from (22.86, 0) to (25.4, -2.54)
  arc A7 centre (2.54, -2.54) radius 2.54 clockwise from (0, -2.54) to (2.54, 0)
  arc A8 centre (2.54, -20.32) radius 2.54 clockwise from (2.54, -22.86) to (0, -20.32)
  point P100 (22.86, -20.32)
  point P110 (22.86, -20.32)
  point P56 (2.54, -2.54)
  point P111 (2.54, -2.54)
  point P57 (2.54, -20.32)
  point P112 (2.54, -20.32)
  point P101 (22.86, -2.54)
  point P113 (22.86, -2.54)
  point P114 (12.7, -11.43)
  coincident P100 P110
  coincident P56 P111
  coincident P57 P112
  coincident P101 P113
  midpoint L11 P114
  vertical L12
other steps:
extrude "Extrude1" new body sketch "Sketch1" along normal blind 0.1 bodies "1X06_ROUND_70"
extrude "Extrude1" new body sketch "Sketch1" along normal blind 0.1 bodies "MOUNTINGHOLE_2.5_PLATED"
extrude "Extrude1" new body sketch "Sketch1" along normal blind 0.1 bodies "FIDUCIAL_1MM"
extrude "Extrude1" new body sketch "Sketch1" along normal blind 0.1 bodies "PCBFEAT-REV-040"
extrude "Extrude1" new body sketch "Sketch1" along normal blind 0.1 bodies "STEMMAQT"
extrude "Extrude1" new body sketch "Sketch1" along normal blind 0.1 bodies "SOLDERJUMPER_ARROW_NOPASTE"
extrude "Extrude1" new body sketch "Sketch1" along normal blind 0.1 bodies "ADAFRUIT_3.5MM"
extrude "Extrude1" new body sketch "Sketch1" along normal blind 0.1 bodies "CHIPLED_0603_NOOUTLINE"
extrude "Extrude1" new body sketch "Sketch1" along normal blind 0.1 bodies "BNO080"
extrude "Extrude1" new body sketch "Sketch1" along normal blind 0.1 bodies "TSSOP16"
extrude "Extrude1" new body sketch "Sketch1" along normal blind 0.1 bodies "0805-NO"
extrude "Extrude1" new body sketch "Sketch1" along normal blind 0.1 bodies "SOT23-5"
extrude "Extrude1" new body sketch "Sketch1" along normal blind 0.1 bodies "0603-NO"
extrude "Extrude1" new body sketch "Sketch1" along normal blind 0.1 bodies "RESPACK_4X0603"
extrude "Extrude1" new body sketch "Sketch1" along normal blind 0.1 bodies "SOT363"
extrude "Extrude1" new body sketch "Sketch1" along normal blind 0.1 bodies "JST_SH4"
extrude "Extrude1" new body sketch "Sketch1" along normal blind 0.1 bodies "XTAL3215"
base_feature "Base Feature1" sketch "Sketch1"
base_feature "Base Feature1" sketch "Sketch1"
base_feature "Base Feature1" sketch "Sketch1"
extrude "Extrude1" new body sketch "Sketch1" along normal blind 1.57 bodies "Board"
base_feature "Base Feature1" sketch "Sketch1"
base_feature "Base Feature1" sketch "Sketch1"
base_feature "Base Feature1" sketch "Sketch1"
base_feature "Base Feature1" sketch "Sketch1"
base_feature "Base Feature1" sketch "Sketch1"
base_feature "Base Feature1" sketch "Sketch1"
base_feature "Base Feature1" sketch "Sketch1"
extrude "Extrude2" sketch "Sketch2" blind 1.57
create_component "CreateComponent1"
sketch "Sketch1" plane through (0, 0, 0) normal (0, 0, 1) x axis (1, 0, 0)
  line L1 (0, 2.54) -> (0, 20.32)
  line L2 (22.86, 0) -> (2.54, 0)
  line L3 (25.4, 20.32) -> (25.4, 2.54)
  line L4 (2.54, 22.86) -> (22.86, 22.86)
  arc A1 centre (2.54, 2.54) radius 2.54 clockwise from (2.54, 0) to (0, 2.54)
  arc A2 centre (22.86, 2.54) radius 2.54 clockwise from (25.4, 2.54) to (22.86, 0)
  arc A3 centre (22.86, 20.32) radius 2.54 clockwise from (22.86, 22.86) to (25.4, 20.32)
  arc A4 centre (2.54, 20.32) radius 2.54 clockwise from (0, 20.32) to (2.54, 22.86)
canvas "Canvas1"
canvas "Canvas2"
